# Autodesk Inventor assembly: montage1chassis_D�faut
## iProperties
Created: 2011-01
Part Number: montage1chassis_D�faut
Document SubType Name: Assembly
Designer: eric
Mass: 436.054 g
Surface Area: 3474.65 cm^2
Volume: 436.054 cm^3
Density: 1 g/cm^3
Author: eric
